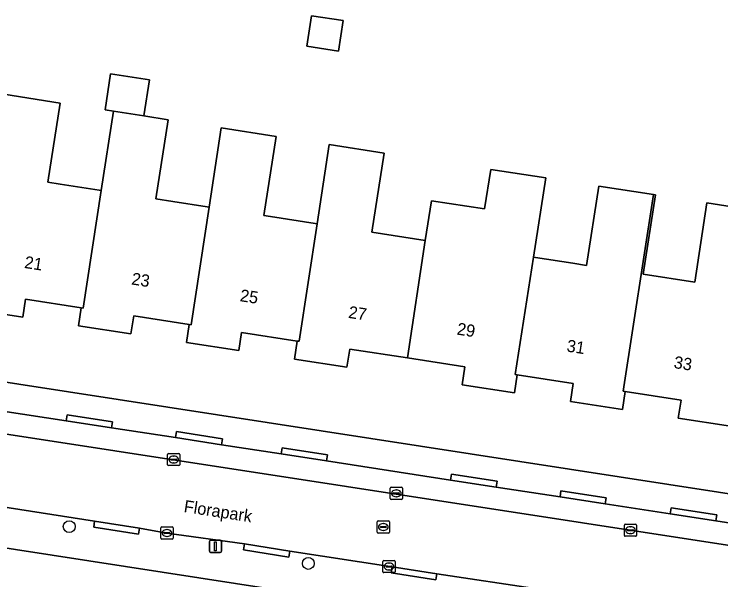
# Model space of a CAD drawing. Extents: x 161483 to 162250, y 379484 to 380833.
# Drawn here: x 161829.9 to 161888.1, y 380635.8 to 380682.4 of the extents above; entities that cross this region are included whole.
import ezdxf

# ---------------------------------------------------------------- set-up
doc = ezdxf.new("R2010")
doc.units = 0
for name, color, linetype in [('IMGEO_Boom', 7, 'Continuous'), ('IMGEO_Erf', 7, 'Continuous'), ('IMGEO_Kolk', 7, 'Continuous'), ('IMGEO_Lichtmast', 7, 'Continuous'), ('IMGEO_Openbare_ruimte_label', 7, 'Continuous'), ('IMGEO_Pand', 7, 'Continuous'), ('IMGEO_Pand_nummerreeks', 7, 'Continuous'), ('IMGEO_Parkeervlak_open', 7, 'Continuous'), ('IMGEO_Rijbaan_lokaal_open', 7, 'Continuous'), ('IMGEO_Rioolput', 7, 'Continuous'), ('IMGEO_Voetpad_open', 7, 'Continuous')]:
    doc.layers.add(name, color=color, linetype=linetype)

msp = doc.modelspace()

# ---------------------------------------------------------------- linework, layer by layer
at = {"layer": 'IMGEO_Boom'}
for centre in [(161834.416, 380640.221), (161854.102, 380637.195)]:
    msp.add_circle(centre, 0.489, dxfattribs=at)
at = {"layer": 'IMGEO_Erf'}
msp.add_lwpolyline([(161856.59, 380679.358), (161853.975, 380679.761), (161854.362, 380682.266), (161856.976, 380681.863)], close=True, dxfattribs=at)
for points in [[(161829.029, 380675.799), (161833.671, 380675.082), (161832.665, 380668.563), (161833.655, 380668.41), (161836.892, 380667.911), (161837.05, 380667.887), (161838.05, 380674.407), (161837.36, 380674.514), (161837.821, 380677.492), (161841.026, 380676.997), (161840.565, 380674.018), (161842.56, 380673.71), (161841.554, 380667.192), (161842.951, 380666.976), (161845.782, 380666.539), (161845.94, 380666.515), (161846.935, 380673.035), (161851.45, 380672.339), (161850.444, 380665.82), (161850.981, 380665.737), (161854.671, 380665.168), (161854.829, 380665.144), (161855.825, 380671.663), (161860.339, 380670.967), (161859.333, 380664.448), (161863.73, 380663.77), (161864.235, 380667.037), (161868.618, 380666.36), (161869.12, 380669.612), (161873.664, 380668.911), (161872.647, 380662.393), (161872.805, 380662.369), (161875.876, 380661.895), (161877.013, 380661.72), (161878.019, 380668.239), (161882.534, 380667.542), (161882.691, 380667.518), (161881.685, 380660.999), (161885.922, 380660.345), (161886.928, 380666.864), (161891.444, 380666.167)], [(161888.871, 380648.486), (161884.566, 380649.149), (161884.794, 380650.631), (161880.192, 380651.339), (161879.964, 380649.858), (161875.678, 380650.518), (161875.906, 380651.999), (161871.294, 380652.709), (161871.066, 380651.228), (161866.76, 380651.89), (161866.998, 380653.37), (161862.255, 380654.1), (161857.517, 380654.83), (161857.28, 380653.35), (161852.964, 380654.014), (161853.192, 380655.496), (161848.6, 380656.203), (161848.371, 380654.721), (161844.076, 380655.383), (161844.304, 380656.864), (161839.721, 380657.57), (161839.493, 380656.088), (161835.178, 380656.753), (161835.406, 380658.234), (161830.823, 380658.939), (161830.595, 380657.458), (161826.303, 380658.114)], [(161797.167, 380657.035), (161908.673, 380639.841), (161916.207, 380638.698), (161924.835, 380637.387), (161925.546, 380637.356)], [(161925.898, 380623.516), (161823.912, 380639.282), (161780.025, 380646.103), (161736.717, 380652.782), (161731.74, 380653.484)]]:
    msp.add_lwpolyline(points, dxfattribs=at)
at = {"layer": 'IMGEO_Kolk'}
for p, q in [((161842.519, 380645.317), (161842.519, 380646.169)), ((161842.594, 380646.243), (161843.446, 380646.243)), ((161843.52, 380646.169), (161843.52, 380645.317)), ((161842.778, 380645.737), (161842.778, 380645.749)), ((161843.216, 380645.7), (161842.818, 380645.7)), ((161842.821, 380645.786), (161843.219, 380645.786)), ((161843.007, 380646.023), (161843.032, 380646.023)), ((161843.262, 380645.749), (161843.262, 380645.737)), ((161843.446, 380645.243), (161842.594, 380645.243)), ((161843.03, 380645.463), (161843.005, 380645.463)), ((161860.852, 380642.531), (161860.852, 380643.383)), ((161860.927, 380643.457), (161861.779, 380643.457)), ((161861.34, 380643.237), (161861.365, 380643.237)), ((161861.853, 380643.383), (161861.853, 380642.531)), ((161861.111, 380642.951), (161861.111, 380642.963)), ((161861.549, 380642.914), (161861.151, 380642.914)), ((161861.154, 380643), (161861.552, 380643)), ((161861.363, 380642.677), (161861.338, 380642.677)), ((161861.595, 380642.963), (161861.595, 380642.951)), ((161861.779, 380642.457), (161860.927, 380642.457)), ((161880.124, 380639.498), (161880.124, 380640.35)), ((161880.199, 380640.424), (161881.051, 380640.424)), ((161881.125, 380640.35), (161881.125, 380639.498)), ((161841.965, 380639.269), (161841.965, 380640.121)), ((161842.04, 380640.195), (161842.892, 380640.195)), ((161842.267, 380639.738), (161842.665, 380639.738)), ((161842.453, 380639.975), (161842.478, 380639.975)), ((161842.966, 380640.121), (161842.966, 380639.269)), ((161880.383, 380639.918), (161880.383, 380639.93)), ((161880.821, 380639.881), (161880.423, 380639.881)), ((161880.426, 380639.967), (161880.824, 380639.967)), ((161880.612, 380640.204), (161880.637, 380640.204)), ((161880.867, 380639.93), (161880.867, 380639.918)), ((161842.892, 380639.195), (161842.04, 380639.195)), ((161842.224, 380639.689), (161842.224, 380639.701)), ((161842.662, 380639.652), (161842.264, 380639.652)), ((161842.476, 380639.415), (161842.451, 380639.415)), ((161842.708, 380639.701), (161842.708, 380639.689)), ((161881.051, 380639.424), (161880.199, 380639.424)), ((161880.635, 380639.644), (161880.61, 380639.644)), ((161860.319, 380637.437), (161861.171, 380637.437)), ((161860.244, 380636.511), (161860.244, 380637.363)), ((161860.503, 380636.931), (161860.503, 380636.943)), ((161860.941, 380636.894), (161860.543, 380636.894)), ((161860.546, 380636.98), (161860.944, 380636.98)), ((161860.732, 380637.217), (161860.757, 380637.217)), ((161860.987, 380636.943), (161860.987, 380636.931)), ((161861.245, 380637.363), (161861.245, 380636.511)), ((161861.171, 380636.437), (161860.319, 380636.437)), ((161860.755, 380636.657), (161860.73, 380636.657))]:
    msp.add_line(p, q, dxfattribs=at)
for points in [[(161842.519, 380645.317), (161842.519, 380646.169)], [(161842.594, 380646.243), (161843.446, 380646.243)], [(161843.52, 380646.169), (161843.52, 380645.317)], [(161843.446, 380645.243), (161842.594, 380645.243)], [(161860.852, 380642.531), (161860.852, 380643.383)], [(161860.927, 380643.457), (161861.779, 380643.457)], [(161861.853, 380643.383), (161861.853, 380642.531)], [(161861.779, 380642.457), (161860.927, 380642.457)], [(161880.124, 380639.498), (161880.124, 380640.35)], [(161880.199, 380640.424), (161881.051, 380640.424)], [(161881.125, 380640.35), (161881.125, 380639.498)], [(161841.965, 380639.269), (161841.965, 380640.121)], [(161842.04, 380640.195), (161842.892, 380640.195)], [(161842.966, 380640.121), (161842.966, 380639.269)], [(161842.892, 380639.195), (161842.04, 380639.195)], [(161881.051, 380639.424), (161880.199, 380639.424)], [(161860.319, 380637.437), (161861.171, 380637.437)], [(161860.244, 380636.511), (161860.244, 380637.363)], [(161861.245, 380637.363), (161861.245, 380636.511)], [(161861.171, 380636.437), (161860.319, 380636.437)]]:
    msp.add_lwpolyline(points, dxfattribs=at)
for centre, radius, start, end in [((161842.596, 380646.167), 0.0765, 91.55205, 178.44795), ((161842.596, 380646.167), 0.0765, 91.55205, 178.44795), ((161843.444, 380646.167), 0.0765, 1.55205, 88.44795), ((161843.444, 380646.167), 0.0765, 1.55205, 88.44795), ((161842.818, 380645.746), 0.0403, 85.87752, 175.75265), ((161842.815, 380645.736), 0.0366, 178.93798, 274.71019), ((161843.219, 380645.743), 0.043, 264.86636, 352.45326), ((161843.223, 380645.748), 0.0386, 1.73085, 96.63898), ((161842.596, 380645.319), 0.0765, 181.55205, 268.44795), ((161842.596, 380645.319), 0.0765, 181.55205, 268.44795), ((161843.444, 380645.319), 0.0765, 271.55205, 358.44795), ((161843.444, 380645.319), 0.0765, 271.55205, 358.44795), ((161860.929, 380643.381), 0.0765, 91.55205, 178.44795), ((161860.929, 380643.381), 0.0765, 91.55205, 178.44795), ((161861.777, 380643.381), 0.0765, 1.55205, 88.44795), ((161861.777, 380643.381), 0.0765, 1.55205, 88.44795), ((161861.151, 380642.96), 0.0403, 85.87752, 175.75265), ((161861.148, 380642.95), 0.0366, 178.93798, 274.71019), ((161861.552, 380642.957), 0.043, 264.86636, 352.45326), ((161861.556, 380642.962), 0.0386, 1.73085, 96.63898), ((161860.929, 380642.533), 0.0765, 181.55205, 268.44795), ((161860.929, 380642.533), 0.0765, 181.55205, 268.44795), ((161861.777, 380642.533), 0.0765, 271.55205, 358.44795), ((161861.777, 380642.533), 0.0765, 271.55205, 358.44795), ((161880.201, 380640.348), 0.0765, 91.55205, 178.44795), ((161880.201, 380640.348), 0.0765, 91.55205, 178.44795), ((161881.049, 380640.348), 0.0765, 1.55205, 88.44795), ((161881.049, 380640.348), 0.0765, 1.55205, 88.44795), ((161842.042, 380640.119), 0.0765, 91.55205, 178.44795), ((161842.042, 380640.119), 0.0765, 91.55205, 178.44795), ((161842.264, 380639.698), 0.0403, 85.87752, 175.75265), ((161842.669, 380639.7), 0.0386, 1.73085, 96.63898), ((161842.89, 380640.119), 0.0765, 1.55205, 88.44795), ((161842.89, 380640.119), 0.0765, 1.55205, 88.44795), ((161880.423, 380639.927), 0.0403, 85.87752, 175.75265), ((161880.42, 380639.917), 0.0366, 178.93798, 274.71019), ((161880.824, 380639.924), 0.043, 264.86636, 352.45326), ((161880.828, 380639.929), 0.0386, 1.73085, 96.63898), ((161842.042, 380639.271), 0.0765, 181.55205, 268.44795), ((161842.042, 380639.271), 0.0765, 181.55205, 268.44795), ((161842.261, 380639.688), 0.0366, 178.93798, 274.71019), ((161842.665, 380639.695), 0.043, 264.86636, 352.45326), ((161842.89, 380639.271), 0.0765, 271.55205, 358.44795), ((161842.89, 380639.271), 0.0765, 271.55205, 358.44795), ((161880.201, 380639.5), 0.0765, 181.55205, 268.44795), ((161880.201, 380639.5), 0.0765, 181.55205, 268.44795), ((161881.049, 380639.5), 0.0765, 271.55205, 358.44795), ((161881.049, 380639.5), 0.0765, 271.55205, 358.44795), ((161860.321, 380637.361), 0.0765, 91.55205, 178.44795), ((161860.321, 380637.361), 0.0765, 91.55205, 178.44795), ((161861.169, 380637.361), 0.0765, 1.55205, 88.44795), ((161861.169, 380637.361), 0.0765, 1.55205, 88.44795), ((161860.543, 380636.94), 0.0403, 85.87752, 175.75265), ((161860.54, 380636.93), 0.0366, 178.93798, 274.71019), ((161860.944, 380636.937), 0.043, 264.86636, 352.45326), ((161860.948, 380636.942), 0.0386, 1.73085, 96.63898), ((161860.321, 380636.513), 0.0765, 181.55205, 268.44795), ((161860.321, 380636.513), 0.0765, 181.55205, 268.44795), ((161861.169, 380636.513), 0.0765, 271.55205, 358.44795), ((161861.169, 380636.513), 0.0765, 271.55205, 358.44795)]:
    msp.add_arc(centre, radius, start, end, dxfattribs=at)
for centre, major_axis, ratio, start_param, end_param in [((161843.006, 380645.743), (-0.387, 0.002), 0.722429, 4.712389, 7.853982), ((161843.031, 380645.743), (-0.39, 0.002), 0.717154, 1.570796, 4.712389), ((161861.339, 380642.957), (-0.387, 0.002), 0.722429, 4.712389, 7.853982), ((161861.364, 380642.957), (-0.39, 0.002), 0.717154, 1.570796, 4.712389), ((161842.452, 380639.695), (-0.387, 0.002), 0.722429, 4.712389, 7.853982), ((161842.477, 380639.695), (-0.39, 0.002), 0.717154, 1.570796, 4.712389), ((161880.611, 380639.924), (-0.387, 0.002), 0.722429, 4.712389, 7.853982), ((161880.636, 380639.924), (-0.39, 0.002), 0.717154, 1.570796, 4.712389), ((161860.731, 380636.937), (-0.387, 0.002), 0.722429, 4.712389, 7.853982), ((161860.756, 380636.937), (-0.39, 0.002), 0.717154, 1.570796, 4.712389)]:
    msp.add_ellipse(centre, major_axis=major_axis, ratio=ratio, start_param=start_param, end_param=end_param, dxfattribs=at)
at = {"layer": 'IMGEO_Lichtmast'}
for p, q in [((161845.952, 380638.198), (161845.952, 380638.998)), ((161845.952, 380638.998), (161845.952, 380638.198)), ((161846.052, 380639.098), (161846.842, 380639.098)), ((161846.842, 380639.098), (161846.052, 380639.098)), ((161846.942, 380638.998), (161846.942, 380638.198)), ((161846.942, 380638.198), (161846.942, 380638.998)), ((161846.842, 380638.098), (161846.052, 380638.098)), ((161846.052, 380638.098), (161846.842, 380638.098))]:
    msp.add_line(p, q, dxfattribs=at)
msp.add_lwpolyline([(161846.372, 380638.973), (161846.522, 380638.973), (161846.522, 380638.223), (161846.372, 380638.223), (161846.372, 380638.973)], dxfattribs=at)
for centre, start, end in [((161846.052, 380638.998), 90, 180), ((161846.052, 380638.998), 90, 180), ((161846.842, 380638.998), 0, 90), ((161846.842, 380638.998), 360, 90), ((161846.052, 380638.198), 180, 270), ((161846.052, 380638.198), 180, 270), ((161846.842, 380638.198), 270, 0), ((161846.842, 380638.198), 270, 0)]:
    msp.add_arc(centre, 0.1, start, end, dxfattribs=at)
at = {"layer": 'IMGEO_Pand'}
for points in [[(161856.59, 380679.358), (161856.976, 380681.863), (161854.362, 380682.266), (161853.975, 380679.761)], [(161838.05, 380674.407), (161840.565, 380674.018), (161841.026, 380676.997), (161837.821, 380677.492), (161837.36, 380674.514)], [(161837.05, 380667.887), (161836.892, 380667.911), (161833.655, 380668.41), (161832.665, 380668.563), (161833.671, 380675.082), (161829.029, 380675.799), (161827.065, 380663.056), (161826.303, 380658.114), (161830.595, 380657.458), (161830.823, 380658.939), (161835.406, 380658.234), (161835.566, 380658.209)], [(161845.94, 380666.515), (161845.782, 380666.539), (161842.951, 380666.976), (161841.554, 380667.192), (161842.56, 380673.71), (161840.565, 380674.018), (161838.05, 380674.407), (161837.05, 380667.887), (161835.566, 380658.209), (161835.406, 380658.234), (161835.178, 380656.753), (161839.493, 380656.088), (161839.721, 380657.57), (161844.304, 380656.864), (161844.463, 380656.84)], [(161854.829, 380665.144), (161854.671, 380665.168), (161850.981, 380665.737), (161850.444, 380665.82), (161851.45, 380672.339), (161846.935, 380673.035), (161845.94, 380666.515), (161844.463, 380656.84), (161844.304, 380656.864), (161844.076, 380655.383), (161848.371, 380654.721), (161848.6, 380656.203), (161853.192, 380655.496), (161853.351, 380655.471)], [(161863.73, 380663.77), (161859.333, 380664.448), (161860.339, 380670.967), (161855.825, 380671.663), (161854.829, 380665.144), (161853.351, 380655.471), (161853.192, 380655.496), (161852.964, 380654.014), (161857.28, 380653.35), (161857.517, 380654.83), (161862.255, 380654.1)], [(161872.647, 380662.393), (161873.664, 380668.911), (161869.12, 380669.612), (161868.618, 380666.36), (161864.235, 380667.037), (161863.73, 380663.77), (161862.255, 380654.1), (161866.998, 380653.37), (161866.76, 380651.89), (161871.066, 380651.228), (161871.294, 380652.709), (161871.14, 380652.733)], [(161882.534, 380667.542), (161878.019, 380668.239), (161877.013, 380661.72), (161875.876, 380661.895), (161872.805, 380662.369), (161872.647, 380662.393), (161871.14, 380652.733), (161871.294, 380652.709), (161875.906, 380651.999), (161875.678, 380650.518), (161879.964, 380649.858), (161880.192, 380651.339), (161880.035, 380651.363)], [(161882.534, 380667.542), (161880.035, 380651.363), (161880.192, 380651.339), (161884.794, 380650.631), (161884.566, 380649.149), (161888.871, 380648.486), (161889.099, 380649.968), (161888.943, 380649.992), (161891.444, 380666.167), (161886.928, 380666.864), (161885.922, 380660.345), (161881.685, 380660.999), (161882.691, 380667.518)]]:
    msp.add_lwpolyline(points, close=True, dxfattribs=at)
at = {"layer": 'IMGEO_Parkeervlak_open'}
for points in [[(161918.986, 380635.854), (161896.349, 380639.345), (161892.581, 380639.926), (161887.663, 380640.685), (161883.909, 380641.264), (161878.553, 380642.09), (161874.831, 380642.664), (161869.575, 380643.474), (161865.816, 380644.054), (161855.606, 380645.629), (161851.871, 380646.205), (161846.947, 380646.964), (161843.17, 380647.547), (161837.894, 380648.36), (161834.174, 380648.934), (161828.937, 380649.734), (161825.202, 380650.315), (161802.414, 380653.775)], [(161799.277, 380652.426), (161896.119, 380637.555), (161921.635, 380633.64)]]:
    msp.add_lwpolyline(points, dxfattribs=at)
at = {"layer": 'IMGEO_Rijbaan_lokaal_open'}
for points in [[(161923.89, 380633.266), (161921.92, 380633.58), (161921.635, 380633.64), (161896.119, 380637.555), (161799.277, 380652.426), (161799.176, 380652.442), (161798.35, 380652.6), (161796.411, 380652.873)], [(161828.567, 380641.917), (161836.508, 380640.681), (161840.209, 380640.087), (161842.462, 380639.696), (161848.844, 380638.801), (161852.574, 380638.203), (161860.998, 380636.913), (161864.674, 380636.339), (161873.104, 380635.067), (161876.861, 380634.467), (161880.077, 380633.98), (161885.647, 380633.107), (161889.34, 380632.533), (161891.34, 380632.201), (161895.056, 380631.647), (161898.375, 380631.13), (161906.524, 380629.872), (161912.467, 380628.951), (161919.648, 380627.838), (161923.889, 380627.212), (161928.578, 380626.472)]]:
    msp.add_lwpolyline(points, dxfattribs=at)
at = {"layer": 'IMGEO_Rioolput'}
for p, q in [((161859.776, 380639.761), (161859.776, 380640.613)), ((161859.851, 380640.687), (161860.703, 380640.687)), ((161860.264, 380640.467), (161860.289, 380640.467)), ((161860.777, 380640.613), (161860.777, 380639.761)), ((161860.035, 380640.181), (161860.035, 380640.193)), ((161860.473, 380640.144), (161860.075, 380640.144)), ((161860.078, 380640.23), (161860.476, 380640.23)), ((161860.287, 380639.907), (161860.262, 380639.907)), ((161860.519, 380640.193), (161860.519, 380640.181)), ((161860.703, 380639.687), (161859.851, 380639.687))]:
    msp.add_line(p, q, dxfattribs=at)
for points in [[(161859.776, 380639.761), (161859.776, 380640.613)], [(161859.851, 380640.687), (161860.703, 380640.687)], [(161860.777, 380640.613), (161860.777, 380639.761)], [(161860.703, 380639.687), (161859.851, 380639.687)]]:
    msp.add_lwpolyline(points, dxfattribs=at)
for centre, radius, start, end in [((161859.853, 380640.611), 0.0765, 91.55205, 178.44795), ((161859.853, 380640.611), 0.0765, 91.55205, 178.44795), ((161860.701, 380640.611), 0.0765, 1.55205, 88.44795), ((161860.701, 380640.611), 0.0765, 1.55205, 88.44795), ((161859.853, 380639.763), 0.0765, 181.55205, 268.44795), ((161859.853, 380639.763), 0.0765, 181.55205, 268.44795), ((161860.075, 380640.19), 0.0403, 85.87752, 175.75265), ((161860.072, 380640.18), 0.0366, 178.93798, 274.71019), ((161860.476, 380640.187), 0.043, 264.86636, 352.45326), ((161860.48, 380640.192), 0.0386, 1.73085, 96.63898), ((161860.701, 380639.763), 0.0765, 271.55205, 358.44795), ((161860.701, 380639.763), 0.0765, 271.55205, 358.44795)]:
    msp.add_arc(centre, radius, start, end, dxfattribs=at)
for centre, major_axis, ratio, start_param, end_param in [((161860.263, 380640.187), (-0.387, 0.002), 0.722429, 4.712389, 7.853982), ((161860.288, 380640.187), (-0.39, 0.002), 0.717154, 1.570796, 4.712389)]:
    msp.add_ellipse(centre, major_axis=major_axis, ratio=ratio, start_param=start_param, end_param=end_param, dxfattribs=at)
at = {"layer": 'IMGEO_Voetpad_open'}
for points in [[(161807.605, 380805.299), (161802.298, 380806.133), (161797.296, 380773.35), (161796.862, 380770.298), (161796.426, 380767.228), (161798.606, 380766.939), (161795.986, 380750), (161793.024, 380730.851), (161790.225, 380712.603), (161787.978, 380697.958), (161781.385, 380654.948), (161780.025, 380646.103), (161823.912, 380639.282), (161925.898, 380623.516)], [(161925.546, 380637.356), (161924.835, 380637.387), (161916.207, 380638.698), (161908.673, 380639.841), (161797.167, 380657.035)], [(161828.937, 380649.734), (161834.174, 380648.934), (161834.25, 380649.428), (161837.97, 380648.854), (161837.894, 380648.36), (161843.17, 380647.547), (161843.246, 380648.041), (161847.023, 380647.458), (161846.947, 380646.964), (161851.871, 380646.205), (161851.947, 380646.699), (161855.682, 380646.123), (161855.606, 380645.629), (161865.816, 380644.054), (161865.891, 380644.547), (161869.65, 380643.969), (161869.575, 380643.474), (161874.831, 380642.664), (161874.906, 380643.157), (161878.629, 380642.592), (161878.553, 380642.09), (161883.909, 380641.264), (161883.985, 380641.758), (161887.739, 380641.179), (161887.663, 380640.685), (161892.581, 380639.926)], [(161889.264, 380632.039), (161885.571, 380632.613), (161885.647, 380633.107), (161880.077, 380633.98), (161876.861, 380634.467), (161876.783, 380633.974), (161873.026, 380634.574), (161873.104, 380635.067), (161864.674, 380636.339), (161864.597, 380635.845), (161860.921, 380636.419), (161860.998, 380636.913), (161852.574, 380638.203), (161852.495, 380637.71), (161848.765, 380638.308), (161848.844, 380638.801), (161842.462, 380639.696), (161840.209, 380640.087), (161840.13, 380639.594), (161836.429, 380640.188), (161836.508, 380640.681), (161828.567, 380641.917)]]:
    msp.add_lwpolyline(points, dxfattribs=at)
for points in [[(161834.174, 380648.934), (161837.894, 380648.36), (161837.97, 380648.854), (161834.25, 380649.428)], [(161843.17, 380647.547), (161846.947, 380646.964), (161847.023, 380647.458), (161843.246, 380648.041)], [(161855.606, 380645.629), (161855.682, 380646.123), (161851.947, 380646.699), (161851.871, 380646.205)], [(161865.816, 380644.054), (161869.575, 380643.474), (161869.65, 380643.969), (161865.891, 380644.547)], [(161878.553, 380642.09), (161878.629, 380642.592), (161874.906, 380643.157), (161874.831, 380642.664)], [(161883.909, 380641.264), (161887.663, 380640.685), (161887.739, 380641.179), (161883.985, 380641.758)], [(161840.209, 380640.087), (161836.508, 380640.681), (161836.429, 380640.188), (161840.13, 380639.594)], [(161848.844, 380638.801), (161848.765, 380638.308), (161852.495, 380637.71), (161852.574, 380638.203)], [(161860.998, 380636.913), (161860.921, 380636.419), (161864.597, 380635.845), (161864.674, 380636.339)]]:
    msp.add_lwpolyline(points, close=True, dxfattribs=at)

# ---------------------------------------------------------------- texts
at = {"layer": 'IMGEO_Openbare_ruimte_label'}
msp.add_text('Florapark', height=1, rotation=351.25384, dxfattribs=at).set_placement((161843.805, 380641.428))
at = {"layer": 'IMGEO_Pand_nummerreeks'}
for s, rotation, p in [('21', 351.25093, (161830.676, 380661.512)), ('23', 351.25093, (161839.494, 380660.154)), ('25', 351.25093, (161848.425, 380658.779)), ('27', 351.25093, (161857.356, 380657.405)), ('29', 351.25093, (161866.287, 380656.03)), ('31', 351.25093, (161875.329, 380654.638)), ('33', 351.24903, (161884.148, 380653.28))]:
    msp.add_text(s, height=1, rotation=rotation, dxfattribs=at).set_placement(p)

doc.saveas('drawing.dxf')
